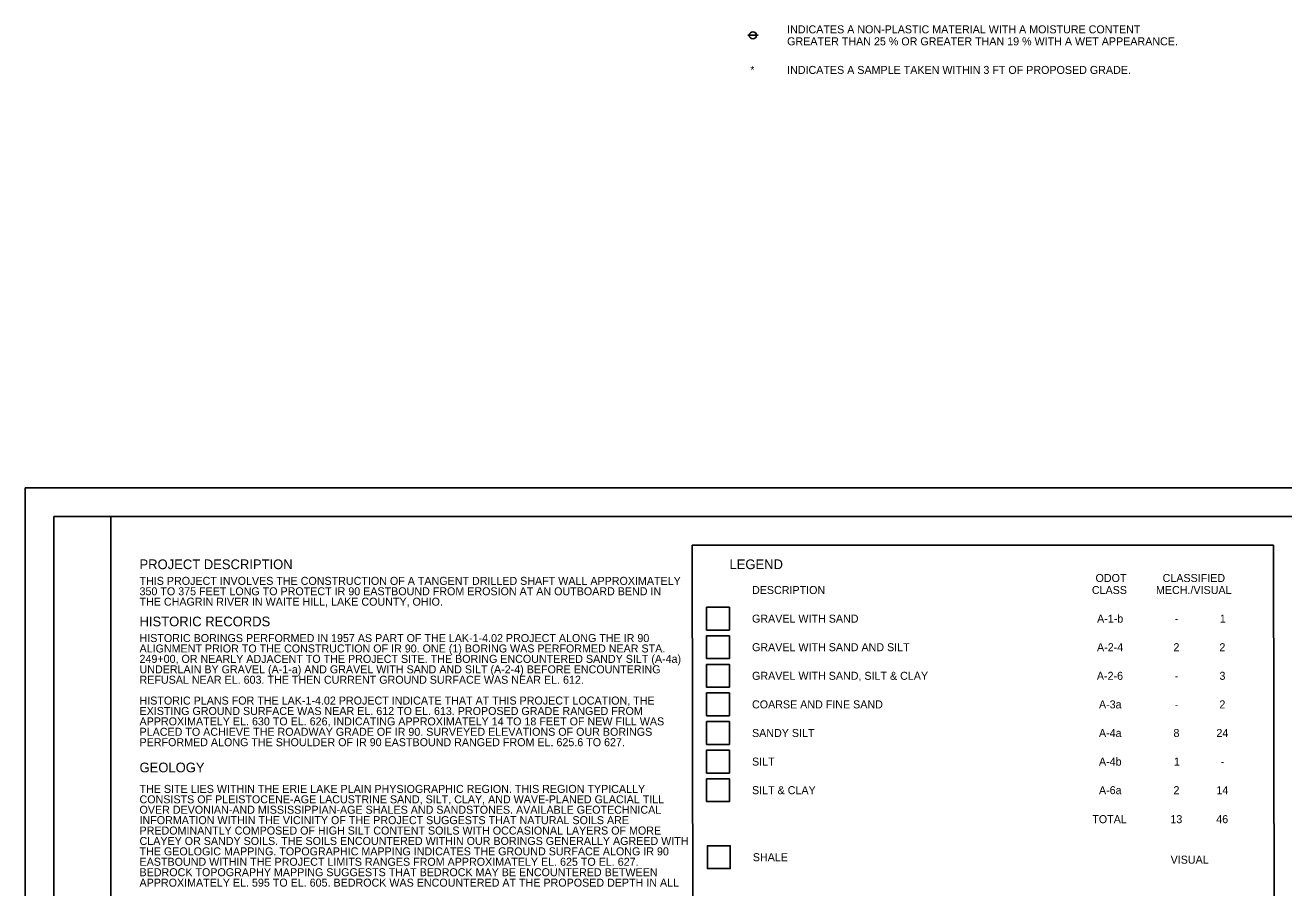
# Model space of a CAD drawing. Extents: x 0 to 34, y 0 to 30.1.
# Drawn here: x 0 to 22.01, y 15.01 to 30.09 of the extents above; entities that cross this region are included whole.
import ezdxf

# ---------------------------------------------------------------- set-up
doc = ezdxf.new("R2010")
doc.units = 0
for name, color, linetype in [('GT_Project_Cells', 7, 'Continuous'), ('SH_Border', 7, 'Continuous'), ('SH_Cut_Line', 7, 'Continuous'), ('SH_Data', 7, 'Continuous'), ('SH_Text', 7, 'Continuous')]:
    doc.layers.add(name, color=color, linetype=linetype)

msp = doc.modelspace()

# ---------------------------------------------------------------- linework, layer by layer
at = {"layer": 'GT_Project_Cells'}
msp.add_line((12.637, 29.915), (12.817, 29.915), dxfattribs=at)
msp.add_circle((12.727, 29.915), 0.0625, dxfattribs=at)
at = {"layer": 'SH_Border'}
for points in [[(0.5, 21.5), (1.5, 21.5), (1.5, 0.5), (0.5, 0.5)], [(1.5, 21.5), (33.5, 21.5), (33.5, 0.5), (1.5, 0.5)]]:
    msp.add_lwpolyline(points, close=True, dxfattribs=at)
at = {"layer": 'SH_Cut_Line'}
msp.add_lwpolyline([(0, 0), (34, 0), (34, 22), (0, 22)], close=True, dxfattribs=at)
at = {"layer": 'SH_Data'}
for p, q in [((11.698, 3), (11.667, 21)), ((21.833, 21), (11.667, 21)), ((21.865, 3), (21.833, 21))]:
    msp.add_line(p, q, dxfattribs=at)
for points in [[(11.917, 19.515), (12.317, 19.515), (12.317, 19.915), (11.917, 19.915)], [(11.917, 19.015), (12.317, 19.015), (12.317, 19.415), (11.917, 19.415)], [(11.917, 18.515), (12.317, 18.515), (12.317, 18.915), (11.917, 18.915)], [(11.917, 18.015), (12.317, 18.015), (12.317, 18.415), (11.917, 18.415)], [(11.917, 17.515), (12.317, 17.515), (12.317, 17.915), (11.917, 17.915)], [(11.917, 17.015), (12.317, 17.015), (12.317, 17.415), (11.917, 17.415)], [(11.917, 16.515), (12.317, 16.515), (12.317, 16.915), (11.917, 16.915)], [(11.931, 15.343), (12.331, 15.343), (12.331, 15.743), (11.931, 15.743)]]:
    msp.add_lwpolyline(points, close=True, dxfattribs=at)
at = {"layer": 'SH_Text'}
for points in [[(11.917, 19.915), (12.317, 19.915), (12.317, 19.515), (11.917, 19.515)], [(11.917, 19.415), (12.317, 19.415), (12.317, 19.015), (11.917, 19.015)], [(11.917, 18.915), (12.317, 18.915), (12.317, 18.515), (11.917, 18.515)], [(11.917, 18.415), (12.317, 18.415), (12.317, 18.015), (11.917, 18.015)], [(11.917, 17.915), (12.317, 17.915), (12.317, 17.515), (11.917, 17.515)], [(11.917, 17.415), (12.317, 17.415), (12.317, 17.015), (11.917, 17.015)], [(11.917, 16.915), (12.317, 16.915), (12.317, 16.515), (11.917, 16.515)], [(11.931, 15.743), (12.331, 15.743), (12.331, 15.343), (11.931, 15.343)]]:
    msp.add_lwpolyline(points, close=True, dxfattribs=at)

# ---------------------------------------------------------------- texts
at = {"layer": 'SH_Data'}
for s, height, p in [('INDICATES A NON-PLASTIC MATERIAL WITH A MOISTURE CONTENT', 0.14, (13.326, 29.95)), ('GREATER THAN 25 % OR GREATER THAN 19 % WITH A WET APPEARANCE.', 0.14, (13.326, 29.74)), ('*', 0.14, (12.681, 29.24)), ('INDICATES A SAMPLE TAKEN WITHIN 3 FT OF PROPOSED GRADE.', 0.14, (13.326, 29.24)), ('PROJECT DESCRIPTION', 0.17, (2, 20.58)), ('LEGEND', 0.17, (12.318, 20.58)), ('ODOT', 0.14, (18.72, 20.355)), ('CLASSIFIED', 0.14, (19.893, 20.355)), ('THIS PROJECT INVOLVES THE CONSTRUCTION OF A TANGENT DRILLED SHAFT WALL APPROXIMATELY ', 0.14, (2, 20.305)), ('350 TO 375 FEET LONG TO PROTECT IR 90 EASTBOUND FROM EROSION AT AN OUTBOARD BEND IN ', 0.14, (2, 20.123)), ('DESCRIPTION', 0.14, (12.712, 20.145)), ('CLASS', 0.14, (18.656, 20.145)), ('MECH./VISUAL', 0.14, (19.777, 20.145)), ('THE CHAGRIN RIVER IN WAITE HILL, LAKE COUNTY, OHIO.', 0.14, (2, 19.941)), ('HISTORIC RECORDS', 0.17, (2, 19.58)), ('GRAVEL WITH SAND', 0.14, (12.712, 19.645)), ('A-1-b', 0.14, (18.747, 19.645)), ('-', 0.14, (20.105, 19.645)), ('1', 0.14, (20.894, 19.645)), ('HISTORIC BORINGS PERFORMED IN 1957 AS PART OF THE LAK-1-4.02 PROJECT ALONG THE IR 90 ', 0.14, (2, 19.305)), ('ALIGNMENT PRIOR TO THE CONSTRUCTION OF IR 90. ONE (1) BORING WAS PERFORMED NEAR STA. ', 0.14, (2, 19.123)), ('GRAVEL WITH SAND AND SILT', 0.14, (12.712, 19.145)), ('A-2-4', 0.14, (18.746, 19.145)), ('2', 0.14, (20.083, 19.145)), ('2', 0.14, (20.886, 19.145)), ('249+00, OR NEARLY ADJACENT TO THE PROJECT SITE. THE BORING ENCOUNTERED SANDY SILT (A-4a) ', 0.14, (2, 18.941)), ('UNDERLAIN BY GRAVEL (A-1-a) AND GRAVEL WITH SAND AND SILT (A-2-4) BEFORE ENCOUNTERING ', 0.14, (2, 18.758)), ('REFUSAL NEAR EL. 603. THE THEN CURRENT GROUND SURFACE WAS NEAR EL. 612.', 0.14, (2, 18.576)), ('GRAVEL WITH SAND, SILT & CLAY', 0.14, (12.712, 18.645)), ('A-2-6', 0.14, (18.743, 18.645)), ('3', 0.14, (20.887, 18.645)), ('-', 0.14, (20.105, 18.645)), ('HISTORIC PLANS FOR THE LAK-1-4.02 PROJECT INDICATE THAT AT THIS PROJECT LOCATION, THE ', 0.14, (2, 18.212)), ('COARSE AND FINE SAND', 0.14, (12.712, 18.145)), ('A-3a', 0.14, (18.78, 18.145)), ('2', 0.14, (20.886, 18.145)), ('EXISTING GROUND SURFACE WAS NEAR EL. 612 TO EL. 613. PROPOSED GRADE RANGED FROM ', 0.14, (2, 18.03)), ('-', 0.14, (20.105, 18.145)), ('APPROXIMATELY EL. 630 TO EL. 626, INDICATING APPROXIMATELY 14 TO 18 FEET OF NEW FILL WAS ', 0.14, (2, 17.848)), ('PLACED TO ACHIEVE THE ROADWAY GRADE OF IR 90. SURVEYED ELEVATIONS OF OUR BORINGS ', 0.14, (2, 17.666)), ('PERFORMED ALONG THE SHOULDER OF IR 90 EASTBOUND RANGED FROM EL. 625.6 TO 627.', 0.14, (2, 17.484)), ('SANDY SILT', 0.14, (12.712, 17.645)), ('A-4a', 0.14, (18.78, 17.645)), ('8', 0.14, (20.083, 17.645)), ('24', 0.14, (20.834, 17.645)), ('GEOLOGY', 0.17, (2, 17.027)), ('SILT', 0.14, (12.712, 17.145)), ('A-4b', 0.14, (18.78, 17.145)), ('1', 0.14, (20.091, 17.145)), ('-', 0.14, (20.909, 17.145)), ('THE SITE LIES WITHIN THE ERIE LAKE PLAIN PHYSIOGRAPHIC REGION. THIS REGION TYPICALLY ', 0.14, (2, 16.667)), ('SILT & CLAY', 0.14, (12.712, 16.645)), ('A-6a', 0.14, (18.78, 16.645)), ('2', 0.14, (20.083, 16.645)), ('14', 0.14, (20.834, 16.645)), ('CONSISTS OF PLEISTOCENE-AGE LACUSTRINE SAND, SILT, CLAY, AND WAVE-PLANED GLACIAL TILL ', 0.14, (2, 16.485)), ('OVER DEVONIAN-AND MISSISSIPPIAN-AGE SHALES AND SANDSTONES. AVAILABLE GEOTECHNICAL ', 0.14, (2, 16.303)), ('PREDOMINANTLY COMPOSED OF HIGH SILT CONTENT SOILS WITH OCCASIONAL LAYERS OF MORE ', 0.14, (2, 15.939)), ('INFORMATION WITHIN THE VICINITY OF THE PROJECT SUGGESTS THAT NATURAL SOILS ARE ', 0.14, (2, 16.121)), ('   TOTAL   ', 0.14, (18.507, 16.138)), ('13', 0.14, (20.029, 16.138)), ('46', 0.14, (20.831, 16.138)), ('CLAYEY OR SANDY SOILS. THE SOILS ENCOUNTERED WITHIN OUR BORINGS GENERALLY AGREED WITH ', 0.14, (2, 15.757)), ('THE GEOLOGIC MAPPING. TOPOGRAPHIC MAPPING INDICATES THE GROUND SURFACE ALONG IR 90 ', 0.14, (2, 15.575)), ('EASTBOUND WITHIN THE PROJECT LIMITS RANGES FROM APPROXIMATELY EL. 625 TO EL. 627. ', 0.14, (2, 15.393)), ('SHALE', 0.14, (12.726, 15.473)), ('VISUAL', 0.14, (20.033, 15.43)), ('BEDROCK TOPOGRAPHY MAPPING SUGGESTS THAT BEDROCK MAY BE ENCOUNTERED BETWEEN ', 0.14, (2, 15.21)), ('APPROXIMATELY EL. 595 TO EL. 605. BEDROCK WAS ENCOUNTERED AT THE PROPOSED DEPTH IN ALL ', 0.14, (2, 15.028))]:
    msp.add_text(s, height=height, dxfattribs=at).set_placement(p)

doc.saveas('drawing.dxf')
